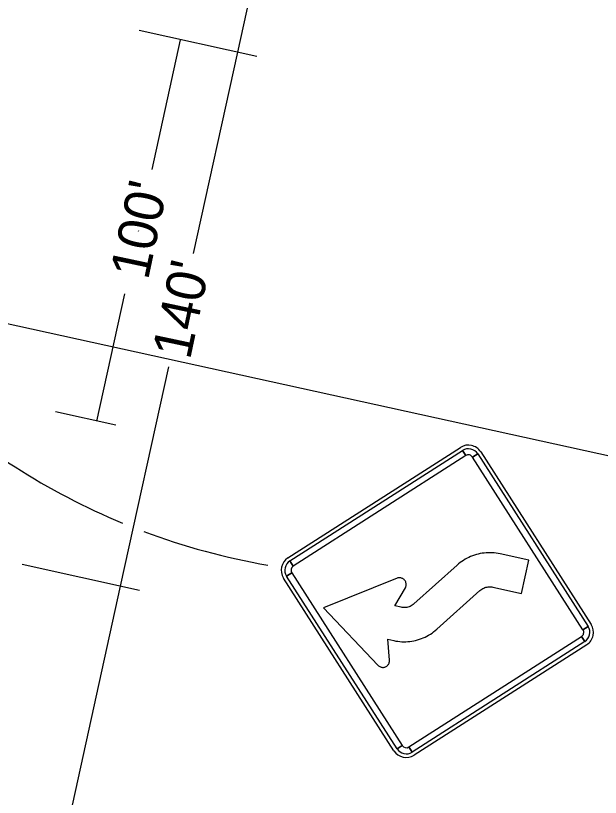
# Model space of a CAD drawing. Extents: x 14104283 to 14121738, y 8635219 to 8671666.
# Drawn here: x 14107738 to 14107887.8, y 8638407.3 to 8638607.6 of the extents above; entities that cross this region are included whole.
import ezdxf

# ---------------------------------------------------------------- set-up
doc = ezdxf.new("R2010")
doc.units = 0
for name, color, linetype in [('Cell', 7, 'Continuous'), ('dsnNonPlotable', 7, 'Continuous'), ('dsnStdLabel', 7, 'Continuous')]:
    doc.layers.add(name, color=color, linetype=linetype)

msp = doc.modelspace()

# ---------------------------------------------------------------- linework, layer by layer
at = {"layer": 'Cell'}
for p, q in [((14107807.76, 8638468.69), (14107851.99, 8638496.98)), ((14107853.33, 8638494.87), (14107852.49, 8638496.19)), ((14107856.38, 8638495.34), (14107855.06, 8638494.49)), ((14107857.17, 8638495.84), (14107885.46, 8638451.62)), ((14107869.45, 8638468.1), (14107862.13, 8638469.71)), ((14107808.27, 8638467.9), (14107809.11, 8638466.58)), ((14107867.57, 8638459.57), (14107869.45, 8638468.1)), ((14107851.11, 8638466.81), (14107840.05, 8638456.9)), ((14107851.5, 8638467.16), (14107851.11, 8638466.81)), ((14107834.92, 8638419.28), (14107806.63, 8638463.51)), ((14107808.73, 8638464.85), (14107807.42, 8638464.01)), ((14107835.72, 8638463.47), (14107816.91, 8638455.91)), ((14107835.91, 8638463.53), (14107835.72, 8638463.47)), ((14107835.19, 8638456.37), (14107837.85, 8638461.02)), ((14107845.89, 8638450.39), (14107856.95, 8638460.3)), ((14107856.95, 8638460.3), (14107857.18, 8638460.49)), ((14107860.25, 8638461.18), (14107867.57, 8638459.57)), ((14107816.91, 8638455.91), (14107830.82, 8638441.18)), ((14107836.75, 8638456.02), (14107835.19, 8638456.37)), ((14107845.51, 8638450.06), (14107845.89, 8638450.39)), ((14107883.35, 8638450.27), (14107884.67, 8638451.11)), ((14107833.78, 8638442.5), (14107833.32, 8638447.83)), ((14107833.32, 8638447.83), (14107834.88, 8638447.49)), ((14107883.82, 8638447.23), (14107882.98, 8638448.54)), ((14107884.32, 8638446.44), (14107840.1, 8638418.14)), ((14107835.71, 8638419.79), (14107837.02, 8638420.63)), ((14107838.75, 8638420.25), (14107839.59, 8638418.94))]:
    msp.add_line(p, q, dxfattribs=at)
for points in [[(14107808.27, 8638467.9), (14107852.49, 8638496.19), (14107853.33, 8638494.87), (14107809.11, 8638466.58), (14107808.27, 8638467.9)], [(14107856.38, 8638495.34), (14107884.67, 8638451.11), (14107883.35, 8638450.27), (14107855.06, 8638494.49), (14107856.38, 8638495.34)], [(14107835.71, 8638419.79), (14107807.42, 8638464.01), (14107808.73, 8638464.85), (14107837.02, 8638420.63), (14107835.71, 8638419.79)], [(14107883.82, 8638447.23), (14107839.59, 8638418.94), (14107838.75, 8638420.25), (14107882.98, 8638448.54), (14107883.82, 8638447.23)]]:
    msp.add_lwpolyline(points, close=True, dxfattribs=at)
for points in [[(14107862.13, 8638469.71), (14107861.62, 8638469.82), (14107861.11, 8638469.89), (14107860.61, 8638469.95), (14107860.1, 8638469.99), (14107859.57, 8638470.01), (14107859.07, 8638470), (14107858.55, 8638469.98), (14107858.05, 8638469.93), (14107857.53, 8638469.86), (14107857.03, 8638469.77), (14107856.52, 8638469.65), (14107856.03, 8638469.52), (14107855.53, 8638469.37), (14107855.05, 8638469.2), (14107854.57, 8638469.01), (14107854.11, 8638468.8), (14107853.64, 8638468.57), (14107853.2, 8638468.32), (14107852.76, 8638468.05), (14107852.33, 8638467.77), (14107851.91, 8638467.47), (14107851.5, 8638467.16)], [(14107837.85, 8638461.02), (14107837.94, 8638461.19), (14107838, 8638461.37), (14107838.04, 8638461.56), (14107838.07, 8638461.75), (14107838.08, 8638461.94), (14107838.06, 8638462.14), (14107838.01, 8638462.32), (14107837.95, 8638462.51), (14107837.87, 8638462.68), (14107837.77, 8638462.84), (14107837.65, 8638462.99), (14107837.52, 8638463.14), (14107837.37, 8638463.26), (14107837.21, 8638463.37), (14107837.03, 8638463.44), (14107836.86, 8638463.51), (14107836.67, 8638463.56), (14107836.47, 8638463.58), (14107836.28, 8638463.58), (14107836.09, 8638463.56), (14107835.91, 8638463.53)], [(14107857.18, 8638460.49), (14107857.42, 8638460.67), (14107857.67, 8638460.81), (14107857.94, 8638460.94), (14107858.21, 8638461.06), (14107858.49, 8638461.14), (14107858.79, 8638461.2), (14107859.07, 8638461.25), (14107859.38, 8638461.26), (14107859.67, 8638461.26), (14107859.96, 8638461.23), (14107860.25, 8638461.18)], [(14107840.05, 8638456.9), (14107839.82, 8638456.71), (14107839.58, 8638456.53), (14107839.34, 8638456.39), (14107839.07, 8638456.26), (14107838.8, 8638456.15), (14107838.51, 8638456.06), (14107838.22, 8638456), (14107837.94, 8638455.96), (14107837.64, 8638455.94), (14107837.34, 8638455.94), (14107837.04, 8638455.97), (14107836.75, 8638456.02)], [(14107834.88, 8638447.49), (14107835.38, 8638447.39), (14107835.89, 8638447.31), (14107836.4, 8638447.26), (14107836.91, 8638447.22), (14107837.43, 8638447.19), (14107837.94, 8638447.21), (14107838.46, 8638447.23), (14107838.96, 8638447.29), (14107839.48, 8638447.35), (14107839.98, 8638447.44), (14107840.48, 8638447.55), (14107840.98, 8638447.68), (14107841.48, 8638447.83), (14107841.96, 8638448), (14107842.44, 8638448.19), (14107842.9, 8638448.4), (14107843.37, 8638448.64), (14107843.81, 8638448.88), (14107844.25, 8638449.15), (14107844.68, 8638449.43), (14107845.09, 8638449.73), (14107845.51, 8638450.06)], [(14107830.82, 8638441.18), (14107830.97, 8638441.04), (14107831.12, 8638440.92), (14107831.28, 8638440.82), (14107831.46, 8638440.75), (14107831.65, 8638440.69), (14107831.84, 8638440.65), (14107832.02, 8638440.64), (14107832.21, 8638440.64), (14107832.41, 8638440.67), (14107832.59, 8638440.71), (14107832.77, 8638440.79), (14107832.94, 8638440.87), (14107833.11, 8638440.98), (14107833.25, 8638441.11), (14107833.38, 8638441.25), (14107833.5, 8638441.41), (14107833.6, 8638441.56), (14107833.68, 8638441.75), (14107833.73, 8638441.92), (14107833.77, 8638442.12), (14107833.79, 8638442.31), (14107833.78, 8638442.5)]]:
    msp.add_lwpolyline(points, dxfattribs=at)
for centre, radius, start, end in [((14107854.01, 8638493.82), 3.75, 32.6103, 122.6105), ((14107854.01, 8638493.82), 2.81, 32.6103, 122.6105), ((14107854.01, 8638493.82), 1.25, 32.6103, 122.6105), ((14107809.78, 8638465.53), 3.75, 122.6105, 212.6102), ((14107809.78, 8638465.53), 2.81, 122.6105, 212.6102), ((14107809.78, 8638465.53), 1.25, 122.6105, 212.6102), ((14107882.3, 8638449.6), 3.75, 302.61, 32.6103), ((14107882.3, 8638449.6), 1.25, 302.61, 32.6103), ((14107882.3, 8638449.6), 2.81, 302.61, 32.6103), ((14107838.08, 8638421.3), 3.75, 212.6104, 302.61), ((14107838.08, 8638421.3), 2.81, 212.6104, 302.61), ((14107838.08, 8638421.3), 1.25, 212.6104, 302.61)]:
    msp.add_arc(centre, radius, start, end, dxfattribs=at)
at = {"layer": 'dsnNonPlotable'}
msp.add_lwpolyline([(14107218.44, 8638642.33), (14107554.83, 8640173.31), (14108541.3, 8639956.56), (14108204.91, 8638425.58)], close=True, dxfattribs=at)
at = {"layer": 'dsnStdLabel'}
for p, q in [((14107794.91, 8638598.19), (14107837.82, 8638793.53)), ((14107799.79, 8638597.11), (14107769.68, 8638603.73)), ((14107772.96, 8638568.19), (14107780.25, 8638601.41)), ((14107783.58, 8638546.62), (14107794.91, 8638598.19)), ((14107769.48, 8638552.35), (14107769.53, 8638552.57)), ((14107758.8, 8638503.73), (14107765.95, 8638536.3)), ((14107764.87, 8638461.45), (14107777.21, 8638517.64)), ((14107763.68, 8638502.66), (14107748.22, 8638506.06)), ((14107769.75, 8638460.37), (14107739.64, 8638466.99)), ((14107742.04, 8638357.53), (14107764.87, 8638461.45))]:
    msp.add_line(p, q, dxfattribs=at)
for start, end in [(227.1647, 247.5016), (249.4154, 260.2176)]:
    msp.add_arc((14107832.4, 8638639.47), 175.19, start, end, dxfattribs=at)

# ---------------------------------------------------------------- texts
for s, p in [("100'", (14107771.9, 8638539.62)), ("140'", (14107782.66, 8638519.2))]:
    msp.add_text(s, height=10, rotation=78.0531, dxfattribs=at).set_placement(p)

doc.saveas('drawing.dxf')
